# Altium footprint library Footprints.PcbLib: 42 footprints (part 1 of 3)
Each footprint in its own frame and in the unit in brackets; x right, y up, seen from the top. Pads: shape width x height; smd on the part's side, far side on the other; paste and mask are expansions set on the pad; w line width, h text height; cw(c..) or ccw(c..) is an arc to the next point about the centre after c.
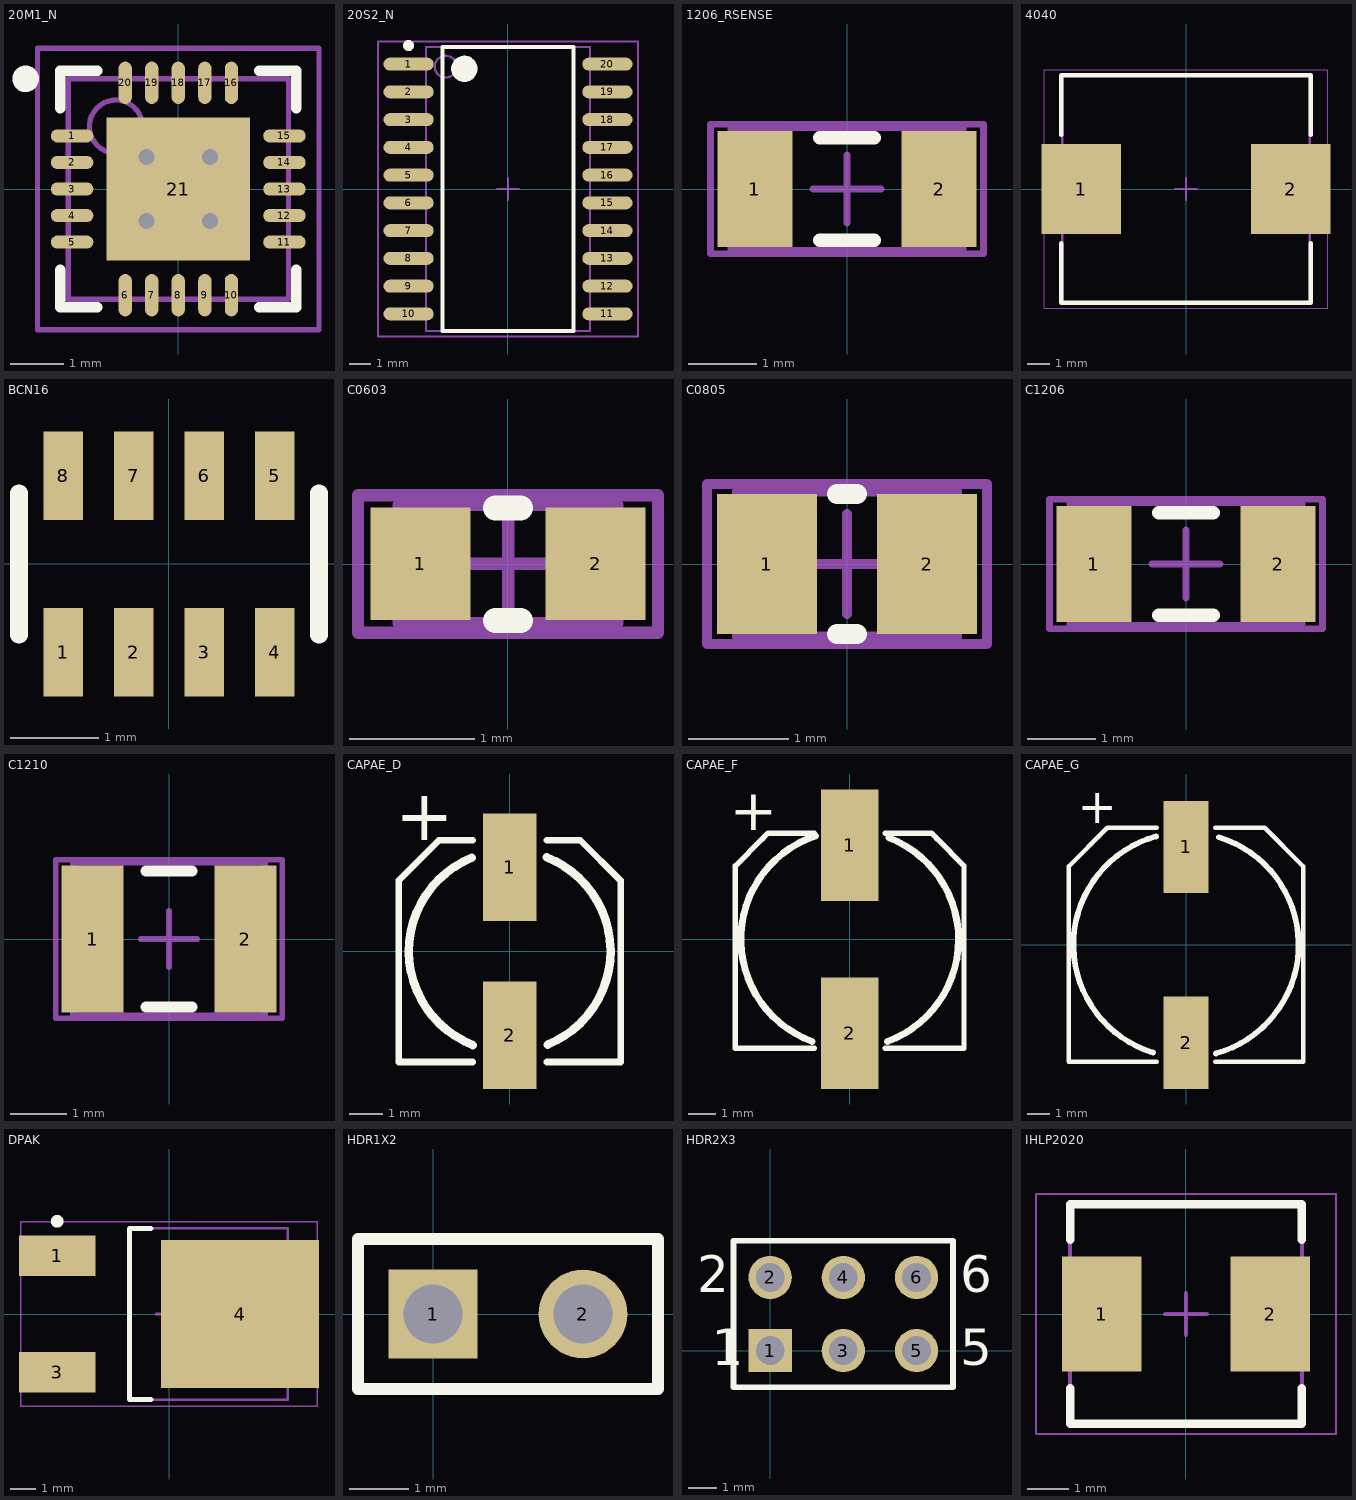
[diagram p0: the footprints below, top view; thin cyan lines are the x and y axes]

## 20M1_N [mm] "QFN, 20-Leads, Body 4x4mm, Pitch 0.5mm, IPC Medium Density"
height 0.8
pads (21):
  oval 0.8x0.25 smd: 1(-2,1) 2(-2,0.5) 3(-2,0) 4(-2,-0.5) 5(-2,-1) 11(2,-1) 12(2,-0.5) 13(2,0) 14(2,0.5) 15(2,1)
  oval 0.25x0.8 smd: 6(-1,-2) 7(-0.5,-2) 8(0,-2) 9(0.5,-2) 10(1,-2) 16(1,2) 17(0.5,2) 18(0,2) 19(-0.5,2) 20(-1,2)
  rect 2.7x2.7 smd mask+0: 21(0,0)
via -0.6,0.6 diameter 0.7 hole 0.3
via 0.6,0.6 diameter 0.7 hole 0.3
via -0.6,-0.6 diameter 0.7 hole 0.3
via 0.6,-0.6 diameter 0.7 hole 0.3
Top Overlay:
  circle w0.25: c-2.875,2.075 r0.125
  lines w0.2: -2.225,-1.525 -2.225,-2.225 -1.525,-2.225 ; -2.225,1.525 -2.225,2.225 -1.525,2.225 ; 1.525,-2.225 2.225,-2.225 2.225,-1.525 ; 1.525,2.225 2.225,2.225 2.225,1.525
Mechanical 13:
  circle w0.1: c-1.175,1.175 r0.5
  lines w0.1: -2.075,-2.075 -2.075,2.075 2.075,2.075 2.075,-2.075 -2.075,-2.075
Mechanical 15:
  lines w0.1: -0.5,0 0.5,0 ; 0,-0.5 0,0.5 ; -2.65,-2.65 -2.65,2.65 2.65,2.65 2.65,-2.65 -2.65,-2.65
3D body: height 0.78, standoff -0.02, extent -2.01,-2.01 2.01,2.01

## 20S2_N [mm] "SOIC, 20-Leads, Body 12.8x7.5mm, Pitch 1.27mm, IPC Medium Density"
height 2.65
pads (20):
  oval 2.3x0.6 smd: 1(-4.55,5.715) 2(-4.55,4.445) 3(-4.55,3.175) 4(-4.55,1.905) 5(-4.55,0.635) 6(-4.55,-0.635) 7(-4.55,-1.905) 8(-4.55,-3.175) 9(-4.55,-4.445) 10(-4.55,-5.715) 11(4.55,-5.715) 12(4.55,-4.445) 13(4.55,-3.175) 14(4.55,-1.905) 15(4.55,-0.635) 16(4.55,0.635) 17(4.55,1.905) 18(4.55,3.175) 19(4.55,4.445) 20(4.55,5.715)
Top Overlay:
  circle w0.25: c-4.55,6.565 r0.125
  circle w0.6: c-2,5.5 r0.3
  lines w0.2: -3,-6.5 -3,6.5 3,6.5 3,-6.5 -3,-6.5
Mechanical 13:
  circle w0.1: c-2.85,5.6 r0.5
  lines w0.1: -3.75,-6.5 -3.75,6.5 3.75,6.5 3.75,-6.5 -3.75,-6.5
Mechanical 15:
  lines w0.1: -0.5,0 0.5,0 ; 0,-0.5 0,0.5 ; -5.95,-6.75 -5.95,6.75 5.95,6.75 5.95,-6.75 -5.95,-6.75
3D body: height 2.65, standoff 0, extent -3.75,-6.5 3.75,6.5

## 1206_RSENSE [mm] "Chip Capacitor, Body 3.2x1.6mm, IPC High Density"
height 1.3
pads (4):
  rect 1.1x1.7 smd: 1(-1.35,0) 2(1.35,0)
  rect 0.1x0.1 smd paste+0 mask+0: 3(-0.9,-0.8) 4(0.9,-0.8)
Top Overlay:
  lines w0.2: -0.4,-0.75 0.4,-0.75 ; -0.4,0.75 0.4,0.75
Mechanical 13:
  lines w0.1: -1.7,-0.9 1.7,-0.9 1.7,0.9 -1.7,0.9 -1.7,-0.9
Mechanical 15:
  lines w0.1: -0.5,0 0.5,0 ; 0,-0.5 0,0.5 ; -2,-0.95 2,-0.95 2,0.95 -2,0.95 -2,-0.95
3D body: height 1.3, standoff 0, extent -1.7,-0.9 1.7,0.9

## 4040 [mm] "Precision Wire Wound Inductor, 2-Leads, Body 10.92x10.30mm, IPC Medium Density"
height 4
pads (2):
  rect 3.6x4.1 smd: 1(-4.75,0) 2(4.75,0)
Top Overlay:
  lines w0.2: -5.65,-2.45 -5.65,-5.15 5.65,-5.15 5.65,-2.45 ; -5.65,2.45 -5.65,5.15 5.65,5.15 5.65,2.45
Mechanical 13:
  lines w0.1: -5.61,-5.15 -5.61,5.15 5.61,5.15 5.61,-5.15 -5.61,-5.15
Mechanical 15:
  lines w0.05: -6.425,-5.4 -6.425,5.4 6.425,5.4 6.425,-5.4 -6.425,-5.4
  lines w0.1: -0.5,0 0.5,0 ; 0,-0.5 0,0.5
3D body: height 4, standoff 0, extent -5.61,-5.15 5.61,5.15

## BCN16 [mm]
height 0.5
pads (8):
  rect 0.45x1 smd: 1(-1.2,-1) 2(-0.4,-1) 3(0.4,-1) 4(1.2,-1) 5(1.2,1) 6(0.4,1) 7(-0.4,1) 8(-1.2,1)
Top Overlay:
  lines w0.2: -1.7,-0.8 -1.7,0.8 ; 1.7,-0.8 1.7,0.8
3D body: height 0.5, standoff 0, extent -1.6,-0.8 1.6,0.8

## C0603 [mm] "Chip Capacitor, Body 1.6x0.8mm, IPC High Density"
height 1.3
pads (2):
  rect 0.8x0.9 smd: 1(-0.7,0) 2(0.7,0)
Top Overlay:
  lines w0.2: -0.1,-0.45 0.1,-0.45 ; -0.1,0.45 0.1,0.45
Mechanical 13:
  lines w0.1: -0.875,-0.475 0.875,-0.475 0.875,0.475 -0.875,0.475 -0.875,-0.475
Mechanical 15:
  lines w0.1: -0.475,0 0.475,0 ; 0,-0.475 0,0.475 ; -1.2,-0.55 1.2,-0.55 1.2,0.55 -1.2,0.55 -1.2,-0.55
3D body: height 0.55, standoff 0, extent -0.8,-0.4 0.8,0.4

## C0805 [mm] "Chip Capacitor, Body 2.0x1.3mm, IPC High Density"
height 1.4
pads (2):
  rect 1x1.4 smd: 1(-0.8,0) 2(0.8,0)
Top Overlay:
  lines w0.2: -0.1,-0.7 0.1,-0.7 ; -0.1,0.7 0.1,0.7
Mechanical 13:
  lines w0.1: -1.1,-0.725 1.1,-0.725 1.1,0.725 -1.1,0.725 -1.1,-0.725
Mechanical 15:
  lines w0.1: -0.5,0 0.5,0 ; 0,-0.5 0,0.5 ; -1.4,-0.8 1.4,-0.8 1.4,0.8 -1.4,0.8 -1.4,-0.8
3D body: height 0.88, standoff 0, extent -0.95,-0.6 1.05,0.6

## C1206 [mm] "Chip Capacitor, Body 3.2x1.6mm, IPC High Density"
height 1.3
pads (2):
  rect 1.1x1.7 smd: 1(-1.35,0) 2(1.35,0)
Top Overlay:
  lines w0.2: -0.4,-0.75 0.4,-0.75 ; -0.4,0.75 0.4,0.75
Mechanical 13:
  lines w0.1: -1.7,-0.9 1.7,-0.9 1.7,0.9 -1.7,0.9 -1.7,-0.9
Mechanical 15:
  lines w0.1: -0.5,0 0.5,0 ; 0,-0.5 0,0.5 ; -2,-0.95 2,-0.95 2,0.95 -2,0.95 -2,-0.95
3D body: height 0.94, standoff 0, extent -1.6,-0.8 1.6,0.8

## C1210 [mm] "Chip Capacitor, Body 3.2x2.5mm, IPC High Density"
height 1.3
pads (2):
  rect 1.1x2.6 smd: 1(-1.35,0) 2(1.35,0)
Top Overlay:
  lines w0.2: -0.4,-1.2 0.4,-1.2 ; -0.4,1.2 0.4,1.2
Mechanical 13:
  lines w0.1: -1.7,-1.35 1.7,-1.35 1.7,1.35 -1.7,1.35 -1.7,-1.35
Mechanical 15:
  lines w0.1: -0.5,0 0.5,0 ; 0,-0.5 0,0.5 ; -2,-1.4 2,-1.4 2,1.4 -2,1.4 -2,-1.4
3D body: height 1.55, standoff 0, extent -1.6,-1.25 1.6,1.25

## CAPAE_D [mm]
height 5.4
pads (2):
  rect 1.6x3.2 smd: 1(0,2.5) 2(0,-2.5)
Top Overlay:
  lines w0.2: -1.1,-3.3 -3.3,-3.3 -3.3,2.1 -2.1,3.3 -1.1,3.3 ; 1.1,-3.3 3.3,-3.3 3.3,2.1 2.1,3.3 1.1,3.3
  lines w0.254: -1.132,2.778 ccw(c0,0) -1.097,-2.792 ; 1.097,2.792 cw(c0,0) 1.132,-2.778
  text "+" at -3.4,3.3 h1.52
3D body: height 0.5, standoff 0, extent -3.3,-3.3 3.3,3.3
3D body: height 5.9, standoff 0.5, extent -3.1,-3.114 3.115,3.114

## CAPAE_F [mm] "8mm DIA"
height 10.5
pads (2):
  rect 2.1x4.1 smd: 1(0,3.45) 2(0,-3.45)
Top Overlay:
  lines w0.2: -1.3,-4 -4.2,-4 -4.2,2.7 -3.2,3.7 -3,3.9 -1.3,3.9 ; 1.3,-4 4.2,-4 4.2,2.7 3.2,3.7 3,3.9 1.3,3.9
  lines w0.254: -1.383,-3.753 cw(c0,0) -1.265,3.795 ; 1.383,-3.753 ccw(c0,0) 1.436,3.733
  text "+" at -4.4,4 h1.52
3D body: height 10.2, standoff 0, extent -4.175,-4.95 4.125,4.95

## CAPAE_G [mm]
height 10.2
pads (2):
  rect 2x4.1 smd: 1(0,4.35) 2(0,-4.35)
Top Overlay:
  lines w0.2: -1.3,-5.2 -5.2,-5.2 -5.2,3.5 -3.5,5.2 -1.3,5.2 ; 1.3,-5.2 5.2,-5.2 5.2,3.5 3.5,5.2 1.3,5.2
  lines w0.254: -1.464,-4.781 cw(c0,0) -1.333,4.819 ; 1.333,-4.819 ccw(c0,0) 1.464,4.781
  text "+" at -4.8,5.4 h1.52
3D body: height 10.2, standoff 0, extent -5.155,-5.8 5.145,5.8

## DPAK [mm] "D-PAK, 3-Pads, Body 6.21x6.73mm (max), IPC Medium Density"
height 2.38
pads (3):
  rect 3x1.6 smd: 1(-4.39,2.29) 3(-4.39,-2.29)
  rect 6.2x5.8 smd: 4(2.79,0)
Top Overlay:
  circle w0.25: c-4.39,3.64 r0.125
  lines w0.2: -0.71,-3.35 -1.55,-3.35 -1.55,3.35 -0.71,3.35
Mechanical 13:
  lines w0.1: -1.55,-3.375 4.67,-3.375 4.67,3.375 -1.55,3.375 -1.55,-3.375
Mechanical 15:
  lines w0.05: -5.825,-3.625 5.825,-3.625 5.825,3.625 -5.825,3.625 -5.825,-3.625
  lines w0.1: -0.5,0 0.5,0 ; 0,-0.5 0,0.5
3D body: height 2.29, standoff -0.12, extent -4.55,-3.245 5.388,3.295

## HDR1X2 [mm] "Connector; Header; 2 Position"
pads (2):
  rect 1.5x1.5 hole 1: 1(0,0)
  round 1.5 hole 1: 2(2.54,0)
Top Overlay:
  lines w0.2: -1.27,-1.27 -1.27,1.27 3.81,1.27 3.81,-1.27 -1.27,-1.27
3D body: height 8.44, standoff -2.54, extent -1.29,-1.225 3.79,1.315

## HDR2X3 [mm] "Connector; Header; 3x2 Position"
pads (6):
  rect 1.5x1.5 hole 1: 1(0,0)
  round 1.5 hole 1: 2(0,2.54) 3(2.54,0) 4(2.54,2.54) 5(5.08,0) 6(5.08,2.54)
Top Overlay:
  lines w0.2: 1.482,-1.27 6.35,-1.27 ; 6.35,-1.27 -1.27,-1.27 -1.27,3.81 6.35,3.81 6.35,-1.27
  text "1" at -2.032,-0.508 h1.27
  text "2" at -2.54,2.032 h1.27
  text "5" at 6.604,-0.508 h1.27
  text "6" at 6.604,2.032 h1.27
3D body: height 8.45, standoff -2.53, extent -1.265,-1.365 6.355,3.715

## IHLP2020 [mm] "Precision Wire Wound Inductor, 2-Leads, Body 5.50x5.20mm, IPC Medium Density"
height 3
pads (2):
  rect 1.915x2.79 smd: 1(-2.037,0) 2(2.038,0)
Top Overlay:
  lines w0.2: -2.8,-1.795 -2.8,-2.65 2.8,-2.65 2.8,-1.795 ; -2.8,1.795 -2.8,2.65 2.8,2.65 2.8,1.795
Mechanical 13:
  lines w0.1: -2.8,-2.65 -2.8,2.65 2.8,2.65 2.8,-2.65 -2.8,-2.65
Mechanical 15:
  lines w0.05: -3.625,-2.9 -3.625,2.9 3.625,2.9 3.625,-2.9 -3.625,-2.9
  lines w0.1: -0.5,0 0.5,0 ; 0,-0.5 0,0.5
3D body: height 2.9, standoff -0.2, extent -2.699,-2.698 2.684,2.699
